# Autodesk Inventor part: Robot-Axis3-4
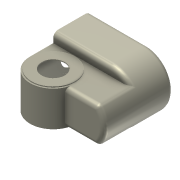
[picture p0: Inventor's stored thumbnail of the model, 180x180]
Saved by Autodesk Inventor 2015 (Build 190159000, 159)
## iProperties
Shininess: 21.0
Length Units: 11269
Angle Units: 11279
Time Units: 11290
Mass Units: 11283
Length Display Precision: 3
Angle Display Precision: 2
Created: 2001-08
Part Number: Robot-Axis3-4
Document SubType Name: ﾓﾃﾞﾘﾝｸﾞ
Designer: Administrator
Density: 1 g/cm^3
Material: Generic
Appearance: Smooth - Ivory
Density: 0.0
Volumn: 0.0
Area: 0.0
PropertySet Name: Model Information
Control State: 0
Master: False
Checked Out: False
Author: Administrator
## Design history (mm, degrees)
sketch "ｽｹｯﾁ1"
  geometry: L1 (-50, 0)-(-50, 68.315); L2 (130, 50)-(-50, 50); L3 (50, 0)-(50, 50); L4 (130, 50)-(130, -20); L5 (45.826, -20)-(130, -20); A1 r 50 centre (0, 0) between (-50, 0) and (50, 0); 1 further point
  constraints: 10 end point, 3 perpendicular, 3 point on circle, 3 tangent, 2 point on line, 1 centre point, 1 coincident, 1 parallel, 1 vertical, 1 other
  dimensions: "d0" = 100 diameter of A1; "d10" = 20 distance from line of L5 A1.centre; "d11" = 180 distance between parallel lines of L4 L1
extrude "押し出し1" new body sketch "ｽｹｯﾁ1" stored distance "d1" = 76; taper "d2" = 0 deg
sketch "ｽｹｯﾁ2"
  geometry: C1 r 50 at (0, 0) reference; C2 r 47 at (0, 0)
  constraints: 1 centre point
  dimensions: "d3" = 3 radial gap between concentric circles of C1 C2
extrude "押し出し2" join sketch "ｽｹｯﾁ2" distance "d4" = 2; taper "d5" = 0 deg
sketch "ｽｹｯﾁ3"
  geometry: L1 (-50, 50)-(-50, 130); L2 (-50, 130)-(130, 130); L3 (-53.41, 90)-(-7.321, 90); L4 (130, 50)-(-50, 50) reference; L5 (-50, 50)-(130, 50); L6 (130, 50)-(130, 130); C1 r 50 at (0, 0) reference
  constraints: 10 end point, 1 collinear, 1 parallel, 1 perpendicular, 1 tangent, 1 vertical
  dimensions: "d6" = 90 distance from line of L3 C1.centre; "d7" = 40 distance between parallel lines of L3 L2; "d8" = 180 distance of L1.end L2.end
extrude "押し出し3" join sketch "ｽｹｯﾁ3" stored distance "d12" = 116; taper "d13" = 0 deg
sketch "ｽｹｯﾁ4"
  geometry: L1 (-20, 130)-(96, 130) reference; L2 (0, 0)-(76, 0) reference; L3 (-37.109, 90)-(114.915, 90); L4 (38, 130)-(38, 36.926); C1 r 37 at (38, 90)
  constraints: 4 end point, 2 point on line, 1 centre point, 1 midpoint, 1 parallel, 1 perpendicular
  dimensions: "d14" = 90 distance between parallel lines of L3 L2; "d15" = 74 diameter of C1
extrude "押し出し4" join sketch "ｽｹｯﾁ4" distance "d16" = 1; taper "d17" = 0 deg
fillet "Chamfer1" dims "d18" = 58
fillet "Chamfer2" dims "d19" = 10
fillet "Chamfer3" dims "d20" = 10
shell "Shell1" dims "d28" = 2
sketch "Sketch5"
  geometry: C1 r 47 at (0, 0) reference
hole "Hole1" sketch "Sketch5" at (0, 0) diameter "d21" = 50; stored, may be unused: countersink angle "d25" = 82 deg, drill point angle "d27" = 118 deg; dims "d22" = 6, "d23" = 4, "d24" = 2, "d26" = 2
sketch "Sketch6"
  geometry: C1 r 37 at (0, 0) reference
hole "Hole2" sketch "Sketch6" at (0, 0) diameter "d29" = 50; stored, may be unused: countersink angle "d33" = 82 deg, drill point angle "d35" = 118 deg; dims "d30" = 6, "d31" = 4, "d32" = 2, "d34" = 2
body "Solid1"
mirror "Mirror1"
